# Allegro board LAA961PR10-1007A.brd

Outline 305.8 x 141.25 mm; copper layers: TOP, GND1, IN1, GND2, IN2, IN3, VCC, IN4, GND3, BOTTOM. Coordinates in mm from the lower left corner of the outline.

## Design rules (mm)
net group 18: nets PECI_EC PECI_EC_R
net group DDI1_LANE_P0_C: nets DDI1_LANE_N0_C DDI1_LANE_P0_C
net group DDI1_LANE_P1_C: nets DDI1_LANE_N1_C DDI1_LANE_P1_C
net group DDI1_LANE_P2_C: nets DDI1_LANE_N2_C DDI1_LANE_P2_C
net group DDI1_LANE_P3_C: nets DDI1_LANE_N3_C DDI1_LANE_P3_C
net group DIFFPAIR28: nets SATA_PRX_DKTX_N0_C SATA_PRX_DKTX_P0_C
net group DIFFPAIR29: nets SATA_PTX_DKRX_N0_C SATA_PTX_DKRX_P0_C
net group DOCK_DCIN_IS: nets DOCK_DCIN_IS+ DOCK_DCIN_IS-
net group DP2: nets TMDS_CON_CLK TMDS_CON_CLK#
net group DP4: nets PS8338_AUX PS8338_AUX#
net group DPC_DOCK_LANE_1: nets DPC_DOCK_LANE_N1 DPC_DOCK_LANE_P1
net group DPC_DOCK_LANE_2: nets DPC_DOCK_LANE_N2 DPC_DOCK_LANE_P2
net group DPC_DOCK_LANE_3: nets DPC_DOCK_LANE_N3 DPC_DOCK_LANE_P3
net group GPU_SMBCLK: nets GPU_SMBCLK GPU_SMBDAT
net group HDMI_LANE_0: nets HDMI_LANE_N0 HDMI_LANE_P0
net group HDMI_LANE_1: nets HDMI_LANE_N1 HDMI_LANE_P1
net group HDMI_LANE_2: nets HDMI_LANE_N2 HDMI_LANE_P2
net group HDMI_LANE_3: nets HDMI_LANE_N3 HDMI_LANE_P3
net group I2C1_S_VMM: nets I2C1_SCL_VMM I2C1_SDA_VMM
net group LAN_TX0L: nets LAN_TX0+L LAN_TX0-L
net group LAN_TX1L: nets LAN_TX1+L LAN_TX1-L
net group LAN_TX2L: nets LAN_TX2+L LAN_TX2-L
net group LAN_TX3L: nets LAN_TX3+L LAN_TX3-L
net group MDP_CA_DET: nets MDP_CA_DET MDP_CA_DET#
net group MINI_DP: nets SW_MDP_AUX#_C SW_MDP_AUX_C
net group PCIE_PRX_MMITX_1_C: nets PCIE_PRX_MMITX_N1_C PCIE_PRX_MMITX_P1_C
net group PCIE_PTX_MMIRX_1_C: nets PCIE_PTX_MMIRX_N1_C PCIE_PTX_MMIRX_P1_C
net group REM_DIODE1_: nets REM_DIODE1_N REM_DIODE1_P
net group REM_DIODE2_: nets REM_DIODE2_N REM_DIODE2_P
net group REM_DIODE4_: nets REM_DIODE4_N REM_DIODE4_P
net group SATA_PRX_DTX_P1_RP_C: nets SATA_PRX_DTX_N1_RP_C SATA_PRX_DTX_P1_RP_C
net group SATA_PTX_DRX_N1_RP_C: nets SATA_PTX_DRX_N1_RP_C SATA_PTX_DRX_P1_RP_C
net group SENSE: nets VCCSENSE VSSSENSE
net group SML1_SMBCLK: nets SML1_SMBCLK SML1_SMBDATA
net group TMDS_CON_0: nets TMDS_CON_N0 TMDS_CON_P0
net group TMDS_CON_1: nets TMDS_CON_N1 TMDS_CON_P1
net group TMDS_CON_2: nets TMDS_CON_N2 TMDS_CON_P2
net group USB3RN4_D: nets USB3RN4_D- USB3RP4_D+
net group USB3RP1_D+: nets USB3RN1_D- USB3RP1_D+
net group USB3T1_C: nets USB3TN1_C USB3TP1_C
net group USB3TP1_D+: nets USB3TN1_D- USB3TP1_D+
net group USB3TP4_D: nets USB3TN4_D- USB3TP4_D+
net group USBP0_R_D: nets USBP0_R_D+ USBP0_R_D-
net group USBP4_D: nets USBP4_D+ USBP4_D-
net group 12: nets PCH_OPI_COMP PCH_PCIE_RCOMP SATA_COMP UIM_CLK UIM_DATA UIM_RESET
net group 15: nets DDR3_DRAMRST# DDR3_DRAMRST#_CPU H_PROCHOT# H_PROCHOT#_R H_THERMTRIP# H_THERMTRIP#_R H_VCCST_PWRGD_XDP PCH_AZ_CODEC_BITCLK THERMATRIP2# XDP_OBS0_R XDP_OBS1_R XDP_OBS2_R XDP_OBS3_R XDP_OBS4_R XDP_OBS5_R XDP_OBS6_R XDP_OBS7_R
net group 20: nets DDI2_LANE_N0 DDI2_LANE_N1 DDI2_LANE_N2 DDI2_LANE_N3 DDI2_LANE_P0 DDI2_LANE_P1 DDI2_LANE_P2 DDI2_LANE_P3 DDR_A_DQS0 DDR_A_DQS1 DDR_A_DQS2 DDR_A_DQS3 DDR_A_DQS4 DDR_A_DQS5 DDR_A_DQS6 DDR_A_DQS7 DDR_A_DQS#0 DDR_A_DQS#1 DDR_A_DQS#2 DDR_A_DQS#3 DDR_A_DQS#4 DDR_A_DQS#5 DDR_A_DQS#6 DDR_A_DQS#7 DDR_B_DQS0 DDR_B_DQS1 DDR_B_DQS2 DDR_B_DQS3 DDR_B_DQS4 DDR_B_DQS5 DDR_B_DQS6 DDR_B_DQS7 DDR_B_DQS#0 DDR_B_DQS#1 DDR_B_DQS#2 DDR_B_DQS#3 DDR_B_DQS#4 DDR_B_DQS#5 DDR_B_DQS#6 DDR_B_DQS#7 SD_UHS2_D0N SD_UHS2_D0P SD_UHS2_D1N SD_UHS2_D1P
net group CFG: nets CFG0 CFG1 CFG2 CFG3 CFG3_R CFG4 CFG5 CFG6 CFG7 CFG8 CFG9 CFG10 CFG11 CFG12 CFG13 CFG14 CFG15 CFG16 CFG17 CFG18 CFG19 CFG_RCOMP
net group CL_LINK: nets PCH_CL_CLK1 PCH_CL_DATA1 PCH_CL_RST1#
net group CLK: nets CLK_PCI_DOCK CLK_PCI_LPDEBUG CLK_PCI_MEC PCI_CLK_LPC_0 PCI_CLK_LPC_1 SUSCLK
net group CR_LOW: nets DSWODVREN INTRUDER# PCH_DPWROK PCH_INTVRMEN PCH_PCIE_WAKE# PCH_RSMRST#_Q PCH_RTCRST# PM_APWROK SIO_PWRBTN# SIO_RCIN# SRTCRST# SYS_PWROK SYS_RESET#
net group CRT: nets BLUE_DOCK CLK_DDC2_DOCK DAT_DDC2_DOCK GREEN_DOCK HSYNC_DOCK RED_DOCK VSYNC_DOCK
net group DDRA-ADD: nets DDR_A_BS0 DDR_A_BS1 DDR_A_BS2 DDR_A_CAS# DDR_A_MA0 DDR_A_MA1 DDR_A_MA2 DDR_A_MA3 DDR_A_MA4 DDR_A_MA5 DDR_A_MA6 DDR_A_MA7 DDR_A_MA8 DDR_A_MA9 DDR_A_MA10 DDR_A_MA11 DDR_A_MA12 DDR_A_MA13 DDR_A_MA14 DDR_A_MA15 DDR_A_RAS# DDR_A_WE#
net group DDRA-CLK: nets M_CLK_DDR0 M_CLK_DDR1 M_CLK_DDR#0 M_CLK_DDR#1
net group DDRA-CTL: nets DDR_CKE0_DIMMA DDR_CKE1_DIMMA DDR_CS0_DIMMA# DDR_CS1_DIMMA# M_ODT0 M_ODT1
net group DDRB-ADD: nets DDR_B_BS0 DDR_B_BS1 DDR_B_BS2 DDR_B_CAS# DDR_B_MA0 DDR_B_MA1 DDR_B_MA2 DDR_B_MA3 DDR_B_MA4 DDR_B_MA5 DDR_B_MA6 DDR_B_MA7 DDR_B_MA8 DDR_B_MA9 DDR_B_MA10 DDR_B_MA11 DDR_B_MA12 DDR_B_MA13 DDR_B_MA14 DDR_B_MA15 DDR_B_RAS# DDR_B_WE#
net group DDRB-CLK: nets M_CLK_DDR2 M_CLK_DDR3 M_CLK_DDR#2 M_CLK_DDR#3
net group DDRB-CTL: nets DDR_CKE2_DIMMB DDR_CKE3_DIMMB DDR_CS2_DIMMB# DDR_CS3_DIMMB# M_ODT2 M_ODT3
net group DDRD0_9_20: nets DDR_A_D0 DDR_A_D1 DDR_A_D2 DDR_A_D3 DDR_A_D4 DDR_A_D5 DDR_A_D6 DDR_A_D7 DDR_A_D8 DDR_A_D9 DDR_A_D10 DDR_A_D11 DDR_A_D12 DDR_A_D13 DDR_A_D14 DDR_A_D15 DDR_A_D32 DDR_A_D33 DDR_A_D34 DDR_A_D35 DDR_A_D36 DDR_A_D37 DDR_A_D38 DDR_A_D39 DDR_A_D40 DDR_A_D41 DDR_A_D42 DDR_A_D43 DDR_A_D44 DDR_A_D45 DDR_A_D46 DDR_A_D47 DDR_B_D0 DDR_B_D1 DDR_B_D2 DDR_B_D3 DDR_B_D4 DDR_B_D5 DDR_B_D6 DDR_B_D7 DDR_B_D8 DDR_B_D9 DDR_B_D10 DDR_B_D11 DDR_B_D12 DDR_B_D13 DDR_B_D14 DDR_B_D15 DDR_B_D32 DDR_B_D33 DDR_B_D34 DDR_B_D35 DDR_B_D36 DDR_B_D37 DDR_B_D38 DDR_B_D39 DDR_B_D40 DDR_B_D41 DDR_B_D42 DDR_B_D43 DDR_B_D44 DDR_B_D45 DDR_B_D46 DDR_B_D47
net group DDRD1_9_20: nets DDR_A_D16 DDR_A_D17 DDR_A_D18 DDR_A_D19 DDR_A_D20 DDR_A_D21 DDR_A_D22 DDR_A_D23 DDR_A_D24 DDR_A_D25 DDR_A_D26 DDR_A_D27 DDR_A_D28 DDR_A_D29 DDR_A_D30 DDR_A_D31 DDR_A_D48 DDR_A_D49 DDR_A_D50 DDR_A_D51 DDR_A_D52 DDR_A_D53 DDR_A_D54 DDR_A_D55 DDR_A_D56 DDR_A_D57 DDR_A_D58 DDR_A_D59 DDR_A_D60 DDR_A_D61 DDR_A_D62 DDR_A_D63 DDR_B_D16 DDR_B_D17 DDR_B_D18 DDR_B_D19 DDR_B_D20 DDR_B_D21 DDR_B_D22 DDR_B_D23 DDR_B_D24 DDR_B_D25 DDR_B_D26 DDR_B_D27 DDR_B_D28 DDR_B_D29 DDR_B_D30 DDR_B_D31 DDR_B_D48 DDR_B_D49 DDR_B_D50 DDR_B_D51 DDR_B_D52 DDR_B_D53 DDR_B_D54 DDR_B_D55 DDR_B_D56 DDR_B_D57 DDR_B_D58 DDR_B_D59 DDR_B_D60 DDR_B_D61 DDR_B_D62 DDR_B_D63
net group DP: nets CPU_DPB_AUX CPU_DPB_AUX# CPU_DPC_AUX CPU_DPC_AUX# PS8338_N0 PS8338_N0_C PS8338_N1 PS8338_N1_C PS8338_N2 PS8338_N2_C PS8338_N3 PS8338_N3_C PS8338_P0 PS8338_P0_C PS8338_P1 PS8338_P1_C PS8338_P2 PS8338_P2_C PS8338_P3 PS8338_P3_C VMM2320_AUX VMM2320_AUX# VMM2320_AUX#_C VMM2320_AUX_C VMM2320_N0 VMM2320_N0_C VMM2320_N1 VMM2320_N1_C VMM2320_N2 VMM2320_N2_C VMM2320_N3 VMM2320_N3_C VMM2320_P0 VMM2320_P0_C VMM2320_P1 VMM2320_P1_C VMM2320_P2 VMM2320_P2_C VMM2320_P3 VMM2320_P3_C
net group DPB: nets DPB_CA_DET DPB_CA_DET# DPB_DOCK_AUX DPB_DOCK_AUX# DPB_DOCK_LANE_N0 DPB_DOCK_LANE_N1 DPB_DOCK_LANE_N2 DPB_DOCK_LANE_N3 DPB_DOCK_LANE_P0 DPB_DOCK_LANE_P1 DPB_DOCK_LANE_P2 DPB_DOCK_LANE_P3 DPB_LANE_N0 DPB_LANE_N0_C DPB_LANE_N1 DPB_LANE_N1_C DPB_LANE_N2 DPB_LANE_N2_C DPB_LANE_N3 DPB_LANE_N3_C DPB_LANE_P0 DPB_LANE_P0_C DPB_LANE_P1 DPB_LANE_P1_C DPB_LANE_P2 DPB_LANE_P2_C DPB_LANE_P3 DPB_LANE_P3_C SW_DPB_AUX SW_DPB_AUX# SW_DPB_AUX#_C SW_DPB_AUX_C VMM_DPB_CTRLCLK VMM_DPB_CTRLDAT
net group DPC: nets DPC_CA_DET DPC_CA_DET# DPC_DOCK_AUX DPC_DOCK_AUX# DPC_DOCK_LANE_N0 DPC_DOCK_LANE_P0 DPC_LANE_N0 DPC_LANE_N0_C DPC_LANE_N1 DPC_LANE_N1_C DPC_LANE_N2 DPC_LANE_N2_C DPC_LANE_N3 DPC_LANE_N3_C DPC_LANE_P0 DPC_LANE_P0_C DPC_LANE_P1 DPC_LANE_P1_C DPC_LANE_P2 DPC_LANE_P2_C DPC_LANE_P3 DPC_LANE_P3_C SW_DPC_AUX SW_DPC_AUX# SW_DPC_AUX#_C SW_DPC_AUX_C VMM_DPC_CTRLCLK VMM_DPC_CTRLDAT
net group EDP: nets EDP_CPU_AUX EDP_CPU_AUX# EDP_CPU_AUX#_C EDP_CPU_AUX_C EDP_CPU_LANE_N0 EDP_CPU_LANE_N0_C EDP_CPU_LANE_N1 EDP_CPU_LANE_N1_C EDP_CPU_LANE_P0 EDP_CPU_LANE_P0_C EDP_CPU_LANE_P1 EDP_CPU_LANE_P1_C
net group HDA: nets PCH_AZ_BITCLK PCH_AZ_CODEC_RST# PCH_AZ_CODEC_SDIN0 PCH_AZ_CODEC_SDOUT PCH_AZ_CODEC_SYNC PCH_AZ_RST# PCH_AZ_SDIN0_R PCH_AZ_SDOUT PCH_AZ_SYNC
net group HDMI: nets CPU_DPB_CTRLCLK CPU_DPB_CTRLDAT DDI1_LANE_N0 DDI1_LANE_N1 DDI1_LANE_N2 DDI1_LANE_N3 DDI1_LANE_P0 DDI1_LANE_P1 DDI1_LANE_P2 DDI1_LANE_P3
net group HEADPHONE JACK: nets AUD_HP_OUT_L AUD_HP_OUT_R AUD_OUT_L AUD_OUT_R
net group LAN-NO REFER: nets NB_LAN_TX0+ NB_LAN_TX0- NB_LAN_TX1+ NB_LAN_TX1- NB_LAN_TX2+ NB_LAN_TX2- NB_LAN_TX3+ NB_LAN_TX3-
net group LPC: nets LPC_LAD0 LPC_LAD1 LPC_LAD2 LPC_LAD3 LPC_LFRAME#
net group MDI: nets DOCK_LOM_TRD0+ DOCK_LOM_TRD0- DOCK_LOM_TRD1+ DOCK_LOM_TRD1- DOCK_LOM_TRD2+ DOCK_LOM_TRD2- DOCK_LOM_TRD3+ DOCK_LOM_TRD3- LAN_TX0+ LAN_TX0- LAN_TX1+ LAN_TX1- LAN_TX2+ LAN_TX2- LAN_TX3+ LAN_TX3- SW_LAN_TX0+ SW_LAN_TX0- SW_LAN_TX1+ SW_LAN_TX1- SW_LAN_TX2+ SW_LAN_TX2- SW_LAN_TX3+ SW_LAN_TX3-
net group MINI DP: nets CPU_DPC_CTRLCLK CPU_DPC_CTRLDAT MDP_AUX#_C MDP_AUX_C MDP_LANE_N0_C MDP_LANE_N1_C MDP_LANE_N2_C MDP_LANE_N3_C MDP_LANE_P0_C MDP_LANE_P1_C MDP_LANE_P2_C MDP_LANE_P3_C
net group PCIE: nets PCIE_PRX_GLANTX_N3 PCIE_PRX_GLANTX_N3_C PCIE_PRX_GLANTX_P3 PCIE_PRX_GLANTX_P3_C PCIE_PRX_MMITX_N1 PCIE_PRX_MMITX_P1 PCIE_PRX_SATATX_N6_L0 PCIE_PRX_SATATX_N6_L1 PCIE_PRX_SATATX_P6_L0 PCIE_PRX_SATATX_P6_L1 PCIE_PRX_WIGIGTX_N5 PCIE_PRX_WIGIGTX_P5 PCIE_PRX_WLANTX_N4 PCIE_PRX_WLANTX_P4 PCIE_PTX_GLANRX_N3 PCIE_PTX_GLANRX_N3_C PCIE_PTX_GLANRX_P3 PCIE_PTX_GLANRX_P3_C PCIE_PTX_MMIRX_N1 PCIE_PTX_MMIRX_P1 PCIE_PTX_SATARX_N6_L0 PCIE_PTX_SATARX_N6_L0_C PCIE_PTX_SATARX_N6_L1 PCIE_PTX_SATARX_N6_L1_C PCIE_PTX_SATARX_P6_L0 PCIE_PTX_SATARX_P6_L0_C PCIE_PTX_SATARX_P6_L1 PCIE_PTX_SATARX_P6_L1_C PCIE_PTX_WIGIGRX_N5 PCIE_PTX_WIGIGRX_N5_C PCIE_PTX_WIGIGRX_P5 PCIE_PTX_WIGIGRX_P5_C PCIE_PTX_WLANRX_N4 PCIE_PTX_WLANRX_N4_C PCIE_PTX_WLANRX_P4 PCIE_PTX_WLANRX_P4_C
net group POWER: nets +1.35V_MEM
net group RCOMP: nets SM_RCOMP0 SM_RCOMP1 SM_RCOMP2
net group SATA: nets SATA_PRX_DKTX_N0 SATA_PRX_DKTX_P0 SATA_PRX_DTX_N1 SATA_PRX_DTX_P1 SATA_PTX_DKRX_N0 SATA_PTX_DKRX_P0 SATA_PTX_DRX_N1 SATA_PTX_DRX_P1
net group SD_10_15: nets SD/MMCCD# SD/MMCCLK SD/MMCCLK_R SD/MMCCMD SD/MMCDAT0 SD/MMCDAT1 SD/MMCDAT2 SD/MMCDAT2_R SD/MMCDAT3 SD/MMCDAT3_R SDWP
net group SMB_10: nets BC_CLK_ECE1117 BC_CLK_ECE5048 CHARGER_SMBCLK CHARGER_SMBDAT DDR_XDP_WAN_SMBCLK DDR_XDP_WAN_SMBDAT DOCK_SMB_CLK DOCK_SMB_DAT LAN_SMBCLK LAN_SMBDATA MEM_SMBCLK MEM_SMBDATA PBAT_SMBCLK PBAT_SMBDAT USH_SMBCLK USH_SMBDAT
net group SPI: nets PCH_SPI_CLK PCH_SPI_CS0# PCH_SPI_CS1# PCH_SPI_DIN PCH_SPI_DO PCH_SPI_DO2 PCH_SPI_DO3 SPI_CLK64 SPI_DIN32 SPI_DIN64 SPI_DO32 SPI_DO64 SPI_PCH_CS0#_R SPI_PCH_CS1#_R SPI_PCH_DO2_32 SPI_PCH_DO2_64 SPI_PCH_DO3_32 SPI_PCH_DO3_64
net group SPI_CLK: nets SPI_CLK32
net group SPK: nets INT_SPK_L+ INT_SPK_L- INT_SPK_R+ INT_SPK_R- INT_SPKR_L+ INT_SPKR_L- INT_SPKR_R+ INT_SPKR_R-
net group SRC_CLK: nets CLK_PCIE_LAN CLK_PCIE_LAN# CLK_PCIE_MMI CLK_PCIE_MMI# CLK_PCIE_SATA CLK_PCIE_SATA# CLK_PCIE_WIGIG CLK_PCIE_WIGIG# CLK_PCIE_WLAN CLK_PCIE_WLAN#
net group SVID: nets H_CPU_SVIDALRT# VIDALERT_N VIDSCLK VIDSOUT
net group USB20: nets DOCK_USB3RN1 DOCK_USB3RP1 DOCK_USB3TN1 DOCK_USB3TP1 DOCK_USBP0+ DOCK_USBP0- DOCK_USBP3+ DOCK_USBP3- PS_USBP0_D+ PS_USBP0_D- SW_USB3RN1 SW_USB3RP1 SW_USB3TN1 SW_USB3TP1 SW_USBP0+ SW_USBP0- SW_USBP3+ SW_USBP3- USBP0+ USBP0- USBP1+ USBP1- USBP2+ USBP2- USBP3+ USBP3- USBP3_D+ USBP3_D- USBP4+ USBP4- USBP5+ USBP5- USBP5_D+ USBP5_D- USBP6+ USBP6- USBP7+ USBP7-
net group USB30: nets USB3RN1 USB3RN2 USB3RN2_IO USB3RN2_RP USB3RN4 USB3RP1 USB3RP2 USB3RP2_IO USB3RP2_RP USB3RP4 USB3TN1 USB3TN2 USB3TN4 USB3TN4_C USB3TP1 USB3TP2 USB3TP4 USB3TP4_C
net group WIGIG: nets WIGIG_AUX WIGIG_AUX# WIGIG_AUX#_C WIGIG_AUX_C WIGIG_LANE_N0 WIGIG_LANE_N0_C WIGIG_LANE_N1 WIGIG_LANE_N1_C WIGIG_LANE_N2 WIGIG_LANE_N2_C WIGIG_LANE_N3 WIGIG_LANE_N3_C WIGIG_LANE_P0 WIGIG_LANE_P0_C WIGIG_LANE_P1 WIGIG_LANE_P1_C WIGIG_LANE_P2 WIGIG_LANE_P2_C WIGIG_LANE_P3 WIGIG_LANE_P3_C
nets with their own width: min track width 0.102; nets +CAP_LDO
nets with their own width: min track width 0.254; nets +DCPRRTC +PCH_RTC_VCCSUS3_3 +RTC_CELL_VBAT +VR_CAP +VREFOUT AUD_SENSE_B CLK_BIASREF
nets with their own width: min track width 0.381; nets +PCH_ASATA3PLL +PCH_AUSB3PLL +PCH_VCCACLKPLL +PCH_VCCDSW +PCH_VCCDSW_R +RTC_CELL
nets with their own width: min track width 0.508; nets +0.675V_P +1.05V_M +1.05V_MODPHY_PCH +1.05V_MP +1.05V_RUN +1.05V_RUN_VMM +1.05V_VCCST +1.35V_MEN_P +3.3V_ALW +3.3V_ALW2 +3.3V_ALW_UE2 +3.3V_ALWP +3.3V_RTC_LDO +3.3V_RUN +3.3V_RUN_VDDA +3.3V_RUN_VMM +3.3V_SPI +3.3V_WWAN +5V_ALW +5V_ALW2 +5V_ALWP +5V_RUN +AUX_LDO +COINCELL +DC_IN +DC_IN_SS +DCIN +DCIN_JACK +DIMM1_VREF_DQ +DIMM2_VREF_DQ +DOCK_PWR_BAR +LOM_VCT +NBDOCK_DC_IN_SS +PCH_VCC1P05 +PWR_SRC +PWR_SRC_AC +RSVD_VCC3P3_1 +SD_IO_LDO +SDC_IN +SM_VREF_CA +SM_VREF_CA_DIMM +SM_VREF_DQ0 +SM_VREF_DQ1 +V1.05S_APLLOPI +V1.05SP_B+ +V_DDR_REF +VCC_CORE +VCC_PWR_SRC +VCCIO_OUT +VCCIOA_OUT +VCHGR +VLDOIN_1.35V EDP_COMP GND GNDA GNDA_CHG
nets with their own width: min track width 0.762; nets +1.05V_MODPHY +3.3V_RUN_AUDIO +VDDA_AVDD1
nets with their own width: min track width 1.016; nets +0.9V_LAN +1.2V_LDO +1.05V_VMM_VDD +1.8V_RUN_CARD +3.3V_ALW_PCH +3.3V_CAM +3.3V_LAN +3.3V_M +3.3V_RUN_CARD +3.3V_RUN_VDDIO +3.3V_TP +GND_CHASSIS +PCH_VCCDSW3_3 +SIM_PWR +VDDA_PVDD +VDISPLAY_VCC +VHDMI_VCC RING2 SLEEVE
nets with their own width: min track width 2.032; nets +0.675V_DDR_VTT +1.05V_VMM_VDDTX +3.3V_HDD +3.3V_SUS +3.3V_WLAN +5V_HDD +5V_RUN_AUDIO +BL_PWR_SRC +LCDVDD
nets with their own width: min track width 5.588; nets +PBATT PBATT+_C

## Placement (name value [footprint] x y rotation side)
C33  4.7U_0805_25V6-K  [C_0805]  146.19 136.44 90 top
C42  4.7P_0402_50V8C  [C_0402]  160.42 124.29 90 bottom
C43  4.7P_0402_50V8C  [C_0402]  164.23 124.31 90 bottom
C263  1U_0402_6.3V6K  [C_0402]  69.54 18.38 90 top
C294  0.1U_0402_10V7K  [C_0402]  144.27 127.61 90 top
C295  0.1U_0402_10V7K  [C_0402]  144.47 123.45 270 bottom
C296  0.1U_0402_10V7K  [C_0402]  145.16 127.61 90 top
C297  0.1U_0402_10V7K  [C_0402]  145.35 123.45 270 bottom
C298  0.1U_0402_10V7K  [C_0402]  146.05 127.61 90 top
C299  0.1U_0402_10V7K  [C_0402]  146.24 123.45 270 bottom
C300  0.1U_0402_10V7K  [C_0402]  148.91 123.45 270 bottom
C301  0.1U_0402_10V7K  [C_0402]  149.8 123.45 270 bottom
C302  0.1U_0402_10V7K  [C_0402]  143.58 123.45 270 bottom
C303  0.1U_0402_10V7K  [C_0402]  146.94 127.61 90 top
C304  0.1U_0402_10V7K  [C_0402]  147.13 123.45 270 bottom
C305  0.1U_0402_10V7K  [C_0402]  147.83 127.61 90 top
C306  0.1U_0402_10V7K  [C_0402]  148.02 123.45 270 bottom
C307  0.1U_0402_10V7K  [C_0402]  148.72 127.61 90 top
C308  0.1U_0402_10V7K  [C_0402]  149.61 127.61 90 top
C309  0.1U_0402_10V7K  [C_0402]  150.5 127.61 90 top
C310  0.033U_0402_16V7K  [C_0402]  151.2 125.23 270 bottom
C311  0.033U_0402_16V7K  [C_0402]  150.51 136.26 180 top
C312  0.01U_0402_16V7K  [C_0402]  150.87 133.72 0 top
C313  0.01U_0402_16V7K  [C_0402]  150.87 134.61 0 top
C314  0.01U_0402_16V7K  [C_0402]  150 133.28 180 top
C315  0.01U_0402_16V7K  [C_0402]  150 132.39 180 top
C316  1U_0402_6.3V6K  [C_0402]  172.71 125.28 0 bottom
C317  0.1U_0603_50V7K  [C_0603]  142.5 134.55 0 top
C318  0.1U_0603_50V7K  [C_0603]  144.72 136.58 90 top
C319  4.7P_0402_50V8C  [C_0402]  174.54 124.46 90 bottom
CA5  100P_0402_50V8J  [C_0402]  107.7 126.55 0 bottom
CA6  100P_0402_50V8J  [C_0402]  107.7 125.34 0 bottom
CA7  0.1U_0402_25V6  [C_0402]  102.12 116.59 270 top
CA8  0.1U_0402_25V6  [C_0402]  211.69 68.02 270 top
CA9  10U_0603_6.3V6M  [C_0603]  212.74 67.94 270 top
CA10  4.7U_0603_6.3V6K  [C_0603]  201.7 73.5 180 top
CA11  0.1U_0402_25V6  [C_0402]  202 69.12 180 top
CA16  4.7U_0603_6.3V6K  [C_0603]  210.14 77.11 0 top
CA17  0.1U_0402_25V6  [C_0402]  212.45 75.71 90 top
CA18  4.7U_0603_6.3V6K  [C_0603]  213.5 75.76 90 top
CA19  1000P_0402_50V7K  [C_0402]  203.99 76.58 90 top
CA22  1000P_0402_50V7K  [C_0402]  206.66 76.6 90 top
CA23  1000P_0402_50V7K  [C_0402]  205.77 76.58 90 top
CA24  1000P_0402_50V7K  [C_0402]  204.89 76.59 90 top
CA25  10U_0603_6.3V6M  [C_0603]  215.23 69.88 0 top
CA26  1U_0603_10V4Z  [C_0603]  210.11 66.27 270 top
CA27  0.1U_0402_25V6  [C_0402]  200.63 67.34 0 top
CA28  0.1U_0402_25V6  [C_0402]  200.63 66.47 0 top
CA29  1U_0603_10V6K  [C_0603]  211.66 74.25 0 top
CA30  22P_0402_50V8J  [C_0402]  199.91 74.54 180 top
CA31  1U_0603_10V6K  [C_0603]  200.8 76.24 180 top
CA33  15P_0402_50V8J  [C_0402]  199.95 71.33 180 top
CA35  2.2U_0402_6.3V6M  [C_0402]  211.7 65.33 90 top
CA41  0.1U_0402_25V6  [C_0402]  199.35 63.74 90 top
CA43  4.7U_0603_6.3V6K  [C_0603]  206.34 66.08 270 top
CA44  4.7U_0603_6.3V6K  [C_0603]  207.56 66.02 270 top
CA45  0.1U_0402_25V6  [C_0402]  207.55 76.29 90 top
CA46  10U_0603_6.3V6M  [C_0603]  197.49 79.49 90 top
CA47  0.1U_0402_25V6  [C_0402]  203.1 76.57 90 top
CA48  10U_0603_6.3V6M  [C_0603]  199.19 79.53 90 top
CA49  1U_0603_10V6K  [C_0603]  213.08 73.05 180 top
CA50  0.1U_0402_25V6  [C_0402]  201.77 72.46 180 top
CA51  4.7U_0603_6.3V6K  [C_0603]  208.87 66.18 270 top
CA52  4.7U_0603_6.3V6K  [C_0603]  210.14 75.9 0 top
CA53  4.7U_0603_6.3V6K  [C_0603]  200.08 70.2 270 top
CC1  15P_0402_50V8J  [C_0402]  144.73 63.68 180 bottom
CC2  15P_0402_50V8J  [C_0402]  146.32 60.44 180 bottom
CC3  1U_0402_6.3V6K  [C_0402]  164.07 63.6 180 top
CC4  1U_0402_6.3V6K  [C_0402]  164.07 64.51 180 top
CC5  27P_0402_50V8J  [C_0402]  135.86 60.82 0 bottom
CC6  0.1U_0402_25V6  [C_0402]  175.53 77.08 180 top
CC7  0.1U_0402_25V6  [C_0402]  183.52 78.34 90 bottom
CC8  15P_0402_50V8J  [C_0402]  124.25 100.43 90 top
CC9  33P_0402_50V8J  [C_0402]  193.83 74.68 180 top
CC10  33P_0402_50V8J  [C_0402]  172.76 74.67 180 top
CC11  15P_0402_50V8J  [C_0402]  124.25 99.13 270 top
CC12  12P_0402_50V8J  [C_0402]  163.17 57.98 90 top
CC13  12P_0402_50V8J  [C_0402]  167.58 59.66 180 top
CC14  12P_0402_50V8J  [C_0402]  161.67 55.86 90 top
CC15  12P_0402_50V8J  [C_0402]  165.06 55.77 90 top
CC17  0.1U_0402_25V6  [C_0402]  62.28 65.64 270 top
CC18  0.1U_0402_25V6  [C_0402]  64.56 42.28 180 top
CC19  0.1U_0402_25V6  [C_0402]  65.85 55.98 90 top
CC20  22P_0402_50V8J  [C_0402]  83.76 101.7 0 top
CC21  0.1U_0402_25V6  [C_0402]  67.69 55.98 90 top
CC22  0.1U_0402_25V6  [C_0402]  69.04 38.51 270 top
CC23  22U_0603_6.3V6M  [C_0603]  107.48 76.85 270 top
CC24  100P_0402_50V8J  [C_0402]  95.67 94.67 180 bottom
CC25  2.2U_0402_6.3V6M  [C_0402]  110.47 60.62 90 bottom
CC26  2.2U_0402_6.3V6M  [C_0402]  109.07 60.62 90 bottom
CC27  2.2U_0402_6.3V6M  [C_0402]  117.7 63.05 0 bottom
CC28  2.2U_0402_6.3V6M  [C_0402]  109.4 63.05 180 bottom
CC29  10U_0603_6.3V6M  [C_0603]  111.55 60.57 90 bottom
CC30  10U_0603_6.3V6M  [C_0603]  115.74 60.57 90 bottom
CC31  10U_0603_6.3V6M  [C_0603]  107.99 60.57 90 bottom
CC32  10U_0603_6.3V6M  [C_0603]  114.34 60.57 90 bottom
CC33  10U_0603_6.3V6M  [C_0603]  112.95 60.57 90 bottom
CC34  10U_0603_6.3V6M  [C_0603]  117.52 60.57 90 bottom
CC35  0.1U_0402_25V6  [C_0402]  76.14 82.02 90 top
CC36  22U_0603_6.3V6M  [C_0603]  123.68 58.98 180 top
CC37  1U_0402_6.3V6K  [C_0402]  122.24 76.97 270 top
CC39  330U_D3_2.5VY_R6M  [C_D2]  167.29 62.28 180 bottom
CC40  1U_0402_6.3V6K  [C_0402]  133.09 84.38 180 top
CC41  330U_D3_2.5VY_R6M  [C_D3]  128.24 114.29 0 bottom
CC42  330U_D3_2.5VY_R6M  [C_D3]  138.61 109.72 90 bottom
CC43  1U_0402_6.3V6K  [C_0402]  127.78 97.37 180 top
CC44  1U_0402_6.3V6K  [C_0402]  131.68 83.06 270 top
CC47  22U_0603_6.3V6M  [C_0603]  130.62 96.69 0 bottom
CC48  0.1U_0402_10V7K  [C_0402]  164.96 53.95 90 top
CC49  0.1U_0402_10V7K  [C_0402]  133.16 75.73 180 top
CC50  1U_0402_6.3V6K  [C_0402]  164.04 53.95 90 top
CC51  22U_0603_6.3V6M  [C_0603]  130.62 97.91 0 bottom
CC52  0.1U_0402_10V7K  [C_0402]  159.68 79.21 180 bottom
CC53  1U_0402_6.3V6K  [C_0402]  133.2 82.62 270 top
CC54  0.1U_0402_10V7K  [C_0402]  133.27 79.3 180 top
CC55  22U_0603_6.3V6M  [C_0603]  134.8 97.79 90 bottom
CC56  22U_0603_6.3V6M  [C_0603]  133.53 97.79 90 bottom
CC57  0.1U_0402_10V7K  [C_0402]  130.14 75.03 90 top
CC58  1U_0402_6.3V6K  [C_0402]  133.26 77.14 90 top
CC59  1U_0402_6.3V6K  [C_0402]  131.31 84.38 180 top
CC60  10U_0603_6.3V6M  [C_0603]  125.75 95.72 270 top
CC61  1U_0402_6.3V6K  [C_0402]  131.32 76.43 90 top
CC62  22U_0603_6.3V6M  [C_0603]  158.09 75.66 270 bottom
CC63  22U_0603_6.3V6M  [C_0603]  131.43 78.41 180 top
CC64  22U_0603_6.3V6M  [C_0603]  131.43 79.62 180 top
CC65  1U_0402_6.3V6K  [C_0402]  126.16 58.23 270 top
CC66  0.1U_0402_10V7K  [C_0402]  130.22 83.06 270 top
CC67  100U_1206_6.3V6M  [C_1206]  123.89 98.42 180 bottom
CC68  1U_0402_6.3V6K  [C_0402]  127.39 79.31 270 top
CC69  1U_0402_6.3V6K  [C_0402]  131.25 80.7 180 top
CC70  1U_0402_6.3V6K  [C_0402]  128.44 84.52 270 top
CC71  1U_0402_6.3V6K  [C_0402]  126.03 82.05 270 top
CC72  1U_0402_6.3V6K  [C_0402]  128.8 77.38 0 top
CC73  1U_0402_6.3V6K  [C_0402]  131.5 57.72 270 top
CC77  100U_1206_6.3V6M  [C_1206]  129.16 98.33 90 bottom
CC78  1U_0402_6.3V6K  [C_0402]  128.98 95.95 0 top
CC79  22U_0603_6.3V6M  [C_0603]  124.34 102.48 180 top
CC80  1U_0402_6.3V6K  [C_0402]  142.71 75.26 0 top
CC81  100U_1206_6.3V6M  [C_1206]  119.89 97.08 180 bottom
CC82  1U_0402_6.3V6K  [C_0402]  126 95.56 180 bottom
CC83  100P_0402_50V8J  [C_0402]  93.8 93.62 90 top
CC84  22U_0603_6.3V6M  [C_0603]  126.88 111.18 180 bottom
CC85  22U_0603_6.3V6M  [C_0603]  127.04 94.89 0 top
CC97  0.47U_0402_10V6K  [C_0402]  132.93 74.41 270 top
CC100  1U_0402_6.3V6K  [C_0402]  145.94 76.09 180 top
CC101  0.1U_0402_25V6  [C_0402]  131.09 60.53 0 bottom
CD1  0.1U_0402_25V6  [C_0402]  56.53 33.07 180 top
CD2  1U_0402_6.3V6K  [C_0402]  95.95 32.64 270 top
CD3  1U_0402_6.3V6K  [C_0402]  95.7 23.22 90 top
CD4  1U_0402_6.3V6K  [C_0402]  84.14 23.54 90 top
CD5  2.2U_0402_6.3V6M  [C_0402]  56.53 32.19 180 top
CD6  0.1U_0402_25V6  [C_0402]  65.6 23.47 90 top
CD7  1U_0402_6.3V6K  [C_0402]  81.73 32.64 270 top
CD8  1U_0402_6.3V6K  [C_0402]  92.52 32.64 270 top
CD9  1U_0402_6.3V6K  [C_0402]  81.03 23.47 90 top
CD10  1U_0402_6.3V6K  [C_0402]  85.41 32.64 270 top
CD11  1U_0402_6.3V6K  [C_0402]  90.15 23.56 90 top
CD12  10U_0603_6.3V6M  [C_0603]  82.43 23.23 90 top
CD13  10U_0603_6.3V6M  [C_0603]  85.92 23.23 90 top
CD14  10U_0603_6.3V6M  [C_0603]  83.51 32.88 270 top
CD15  10U_0603_6.3V6M  [C_0603]  87.06 32.88 270 top
CD16  10U_0603_6.3V6M  [C_0603]  90.62 32.88 270 top
CD17  10U_0603_6.3V6M  [C_0603]  89.03 23.23 90 top
CD18  10U_0603_6.3V6M  [C_0603]  87.76 23.23 90 top
CD19  10U_0603_6.3V6M  [C_0603]  94.3 32.88 270 top
CD20  330U_D3_2.5VY_R6M  [C_D3]  104.98 36.57 180 top
CD21  0.022U_0402_16V7K  [C_0402]  56.58 36.3 90 top
CD22  0.1U_0402_25V6  [C_0402]  97.48 23.47 90 top
CD23  2.2U_0402_6.3V6M  [C_0402]  96.59 23.47 90 top
CD24  0.1U_0402_25V6  [C_0402]  121.4 30.53 0 top
CD25  0.1U_0402_25V6  [C_0402]  121.4 31.42 0 top
CD26  0.1U_0402_25V6  [C_0402]  120.54 25.39 180 top
CD27  0.1U_0402_25V6  [C_0402]  120.54 24.44 180 top
CD28  10U_0603_6.3V6M  [C_0603]  121.41 29.45 0 top
CD29  10U_0603_6.3V6M  [C_0603]  120.78 23.3 180 top
CD30  0.1U_0402_25V6  [C_0402]  97.86 11.34 90 top
CD31  2.2U_0402_6.3V6M  [C_0402]  119.19 32.43 90 top
CD32  0.1U_0402_25V6  [C_0402]  120.08 32.43 90 top
CD33  2.2U_0402_6.3V6M  [C_0402]  131.47 31.77 180 top
CD34  0.1U_0402_25V6  [C_0402]  131.47 32.66 180 top
CD35  0.1U_0402_25V6  [C_0402]  137.29 19.89 180 bottom
CD36  0.022U_0402_16V7K  [C_0402]  72.08 24.43 90 top
CD37  1U_0402_6.3V6K  [C_0402]  168.7 23.47 90 top
CD38  1U_0402_6.3V6K  [C_0402]  172.38 23.47 90 top
CD39  1U_0402_6.3V6K  [C_0402]  168.44 32.64 270 top
CD40  1U_0402_6.3V6K  [C_0402]  171.87 32.64 270 top
CD41  1U_0402_6.3V6K  [C_0402]  161.59 23.47 90 top
CD42  1U_0402_6.3V6K  [C_0402]  161.33 32.64 270 top
CD43  1U_0402_6.3V6K  [C_0402]  157.6 32.9 0 top
CD44  1U_0402_6.3V6K  [C_0402]  157.22 21.44 180 bottom
CD45  10U_0603_6.3V6M  [C_0603]  165.27 23.23 90 top
CD46  10U_0603_6.3V6M  [C_0603]  163.11 23.23 90 top
CD47  10U_0603_6.3V6M  [C_0603]  159.68 23.23 90 top
CD48  10U_0603_6.3V6M  [C_0603]  166.54 32.88 270 top
CD49  10U_0603_6.3V6M  [C_0603]  170.22 32.88 270 top
CD50  10U_0603_6.3V6M  [C_0603]  170.48 23.23 90 top
CD51  10U_0603_6.3V6M  [C_0603]  159.55 32.82 270 top
CD52  10U_0603_6.3V6M  [C_0603]  162.98 32.88 270 top
CD53  330U_D3_2.5VY_R6M  [C_D3]  126.27 36.63 180 top
CD54  0.022U_0402_16V7K  [C_0402]  127.82 32.71 270 top
CD55  0.1U_0402_25V6  [C_0402]  173.78 23.47 90 top
CD56  2.2U_0402_6.3V6M  [C_0402]  174.67 23.47 90 top
CD57  0.1U_0402_25V6  [C_0402]  196.4 30.92 0 top
CD58  0.1U_0402_25V6  [C_0402]  196.4 30.03 0 top
CD59  0.1U_0402_25V6  [C_0402]  196.46 25.84 0 top
CD60  0.1U_0402_25V6  [C_0402]  196.46 26.72 0 top
CD61  10U_0603_6.3V6M  [C_0603]  196.66 27.68 90 top
CD62  10U_0603_6.3V6M  [C_0603]  196.47 31.99 0 top
CD63  2.2U_0402_6.3V6M  [C_0402]  191.39 34.39 90 top
CD64  0.1U_0402_25V6  [C_0402]  192.34 34.39 90 top
CE1  10U_0603_6.3V6M  [C_0603]  187.26 93.4 180 top
CE2  0.1U_0402_25V6  [C_0402]  177.02 93.93 270 top
CE3  0.1U_0402_25V6  [C_0402]  189.98 104.07 0 top
CE4  0.1U_0402_10V7K  [C_0402]  172.28 103.86 90 top
CE5  0.1U_0402_25V6  [C_0402]  183.84 108.75 90 top
CE6  0.1U_0402_25V6  [C_0402]  176.13 93.93 270 top
CE7  4.7U_0603_6.3V6K  [C_0603]  190.06 102.86 0 top
CE8  0.047U_0402_16V4Z  [C_0402]  183.45 112 270 top
CE9  33P_0402_50V8J  [C_0402]  182.12 92.56 90 top
CE10  1U_0402_6.3V6K  [C_0402]  217.3 80.7 90 top
CE11  0.1U_0402_25V6  [C_0402]  210.15 83.86 270 top
CE12  1U_0402_6.3V6K  [C_0402]  216.41 80.7 90 top
CE13  0.1U_0402_25V6  [C_0402]  207.86 100.31 0 top
CE14  1U_0402_6.3V6K  [C_0402]  208.63 101.65 90 top
CE15  1U_0402_6.3V6K  [C_0402]  205.12 84.46 270 top
CE16  0.1U_0402_25V6  [C_0402]  216.21 84.13 0 top
CE17  0.1U_0402_25V6  [C_0402]  198.26 90.41 180 top
CE18  0.1U_0402_25V6  [C_0402]  203.01 84.47 270 top
CE19  0.1U_0402_25V6  [C_0402]  198.14 97.78 180 top
CE20  0.1U_0402_25V6  [C_0402]  206 84.46 270 top
CE21  10U_0603_6.3V6M  [C_0603]  216.25 83.06 0 top
CE22  0.1U_0402_25V6  [C_0402]  204.35 99.42 90 top
CE23  0.1U_0402_25V6  [C_0402]  213.03 93.46 0 top
CE24  2200P_0402_50V7K  [C_0402]  212.91 95.32 270 top
CE25  0.1U_0402_25V6  [C_0402]  198.3 86.3 180 top
CE26  2200P_0402_50V7K  [C_0402]  214.32 96.21 270 top
CE27  2200P_0402_50V7K  [C_0402]  213.05 96.43 90 top
CE28  22P_0402_50V8J  [C_0402]  208.36 84.38 180 top
CE29  22P_0402_50V8J  [C_0402]  209.24 82.62 270 top
CE30  1U_0402_6.3V6K  [C_0402]  204.22 80.01 270 top
CE31  4.7U_0603_6.3V6K  [C_0603]  213.17 98.42 0 top
CE32  10U_0603_6.3V6M  [C_0603]  75.31 86.86 180 top
CE34  4.7P_0402_50V8C  [C_0402]  203.14 101.16 90 top
CE35  100P_0402_50V8J  [C_0402]  117.01 81.16 270 top
CE36  0.1U_0402_25V6  [C_0402]  201.17 99.42 90 top
CE37  100P_0402_50V8J  [C_0402]  203.65 38.71 0 bottom
CE38  0.1U_0402_25V6  [C_0402]  210.63 99.18 90 top
CE39  100P_0402_50V8J  [C_0402]  85.64 94.91 90 top
CE40  4700P_0402_25V7K  [C_0402]  215.71 96.21 270 top
CE44  1U_0402_6.3V6K  [C_0402]  212.04 78.17 0 top
CE45  1U_0402_6.3V6K  [C_0402]  209.69 79.04 270 top
CE46  100P_0402_50V8J  [C_0402]  195.34 101.12 0 bottom
CI1  100U_1206_6.3V6M  [C_1206]  70.42 122.8 0 bottom
CI3  0.1U_0402_25V6  [C_0402]  70.98 124.32 0 bottom
CI4  0.1U_0402_10V7K  [C_0402]  66.21 116.61 270 top
CI5  0.1U_0402_10V7K  [C_0402]  67.16 116.61 270 top
CI8  100U_1206_6.3V6M  [C_1206]  246.34 122.01 0 bottom
CI10  0.1U_0402_25V6  [C_0402]  241.89 125.02 90 bottom
CI11  10U_0603_6.3V6M  [C_0603]  241.37 120.23 180 bottom
CI12  0.1U_0402_25V6  [C_0402]  241.06 119.19 180 bottom
CI13  10U_0603_6.3V6M  [C_0603]  60.98 117.02 270 top
CI19  0.1U_0402_25V6  [C_0402]  58.85 119.61 90 bottom
CI27  0.1U_0402_10V7K  [C_0402]  227.59 118.16 270 bottom
CI28  0.1U_0402_10V7K  [C_0402]  226.63 118.16 270 bottom
CI29  0.01U_0402_16V7K  [C_0402]  221.95 85.51 90 top
CI30  0.1U_0402_10V7K  [C_0402]  228.41 81.02 0 top
CI31  0.1U_0402_10V7K  [C_0402]  223.73 86.44 270 top
CI32  0.1U_0402_10V7K  [C_0402]  224.64 86.44 270 top
CI33  0.1U_0402_16V4Z  [C_0402]  219.05 60.58 270 top
CI34  0.1U_0402_16V4Z  [C_0402]  219.28 68.06 180 top
CI35  0.1U_0402_16V4Z  [C_0402]  219.28 68.95 180 top
CI38  0.1U_0402_25V6  [C_0402]  126.37 126.43 270 bottom
CI414  0.1U_0402_25V6  [C_0402]  127.18 131.26 0 bottom
CI415  0.1U_0402_25V6  [C_0402]  130.71 132.43 270 bottom
CI416  0.1U_0402_25V6  [C_0402]  133.37 127.46 180 top
CI417  0.1U_0402_25V6  [C_0402]  133.1 134.14 90 top
CI418  0.1U_0402_25V6  [C_0402]  130.6 134.15 90 top
CI419  0.1U_0402_25V6  [C_0402]  130.24 128.48 90 bottom
CI420  4.7U_0603_6.3V6K  [C_0603]  127.54 128.4 90 bottom
CL1  0.1U_0402_10V7K  [C_0402]  200.63 116.42 180 top
CL2  0.1U_0402_10V7K  [C_0402]  200.63 115.53 180 top
CL3  0.1U_0402_10V7K  [C_0402]  208.68 109.25 270 bottom
CL4  10U_0603_6.3V6M  [C_0603]  208.92 110.39 180 bottom
CL5  0.1U_0402_10V7K  [C_0402]  200.46 111.62 90 top
CL6  0.1U_0402_10V7K  [C_0402]  201.37 111.62 90 top
CL7  1U_0603_10V6K  [C_0603]  215.14 119.6 90 bottom
CL8  0.1U_0402_10V7K  [C_0402]  211.65 110.11 270 top
CL9  0.1U_0402_10V7K  [C_0402]  204.87 120.39 180 top
CL10  0.1U_0402_10V7K  [C_0402]  211.11 114.49 90 bottom
CL11  0.1U_0402_10V7K  [C_0402]  203.34 112.64 180 top
CL12  22U_0603_6.3V6M  [C_0603]  204.76 121.55 180 top
CL13  27P_0402_50V8J  [C_0402]  209.1 108.32 0 top
CL14  27P_0402_50V8J  [C_0402]  211.79 108.32 180 top
CL15  0.1U_0402_10V7K  [C_0402]  211.64 124.01 0 top
CL16  0.47U_0603_10V7K  [C_0603]  269.56 133.9 90 bottom
CL17  0.47U_0603_10V7K  [C_0603]  270.76 133.9 90 bottom
CL18  470P_0402_50V7K  [C_0402]  257.94 125.72 0 bottom
CL19  0.1U_0402_10V7K  [C_0402]  257.94 124.77 0 bottom
CL20  0.47U_0603_10V7K  [C_0603]  275.53 126.86 180 top
CL21  0.47U_0603_10V7K  [C_0603]  276.48 126.86 0 top
CL22  150P_1808_2.5KV8J  [C_1808]  260.53 122.61 0 bottom
CL23  0.1U_0402_10V7K  [C_0402]  197.14 105.59 270 top
CL24  470P_0402_50V7K  [C_0402]  198.74 107.39 0 top
CL25  0.1U_0402_25V6  [C_0402]  209.22 120.34 90 top
CL26  0.1U_0402_25V6  [C_0402]  216.22 127.61 90 bottom
CL27  0.1U_0402_25V6  [C_0402]  222.18 125.02 0 bottom
CMOS1  SHORT PADS~D  [SHORTPADS]  84.17 53.65 270 bottom
CN1  10U_0603_6.3V6M  [C_0603]  221.3 113.34 270 top
CN2  0.1U_0402_25V6  [C_0402]  217.6 110.68 270 top
CN13  1000P_0402_50V7K  [C_0402]  215.84 109.2 180 bottom
CN14  0.1U_0402_25V6  [C_0402]  215.84 108.31 180 bottom
CN15  0.1U_0402_25V6  [C_0402]  216.43 108.74 270 top
CN16  0.1U_0402_25V6  [C_0402]  217.42 108.71 270 top
CN35  0.01U_0402_16V7K  [C_0402]  220.82 109.03 90 bottom
CN36  0.01U_0402_16V7K  [C_0402]  221.73 109.03 90 bottom
CN37  0.01U_0402_16V7K  [C_0402]  222.65 109.06 90 bottom
CN38  0.01U_0402_16V7K  [C_0402]  223.56 109.06 90 bottom
CR1  4.7U_0603_6.3V6K  [C_0603]  20.36 11.89 180 top
CR2  0.1U_0402_25V6  [C_0402]  20.89 23.85 90 top
CR3  0.1U_0402_25V6  [C_0402]  20.07 12.96 180 top
CR4  0.1U_0402_25V6  [C_0402]  27.56 19.56 270 top
CR6  0.1U_0402_25V6  [C_0402]  17.22 17.07 180 top
CR7  4.7U_0603_6.3V6K  [C_0603]  17.91 26.22 270 top
CR8  0.1U_0402_25V6  [C_0402]  17.2 23.87 0 top
CR9  4.7U_0603_6.3V6K  [C_0603]  19.24 26.15 270 top
CR10  0.1U_0402_25V6  [C_0402]  19.95 23.8 180 top
CR13  0.1U_0402_25V6  [C_0402]  29.47 18.74 270 top
CR14  4.7U_0603_6.3V6K  [C_0603]  16.32 11.61 90 top
CR15  0.1U_0402_25V6  [C_0402]  17.43 12.11 90 top
CR17  1U_0402_6.3V6K  [C_0402]  17.91 21.89 90 top
CR18  4.7U_0603_6.3V6K  [C_0603]  28.51 25.43 180 top
CR19  0.1U_0402_25V6  [C_0402]  25.54 24.64 270 top
CR21  0.1U_0402_25V6  [C_0402]  22.7 12.94 90 top
CR22  0.1U_0402_25V6  [C_0402]  21.19 12.94 90 top
CR23  5P_0402_50V8C  [C_0402]  29.38 20.51 270 top
CR24  0.1U_0402_10V7K  [C_0402]  23.31 26.55 270 top
CR25  0.1U_0402_10V7K  [C_0402]  24.2 26.55 270 top
CR26  0.1U_0402_10V7K  [C_0402]  22.42 26.55 270 top
CR27  0.1U_0402_10V7K  [C_0402]  21.53 26.55 270 top
CR31  1U_0402_6.3V6K  [C_0402]  17.22 17.96 180 top
CR34  4.7U_0603_6.3V6K  [C_0603]  17.91 15.45 180 top
CR35  0.1U_0402_25V6  [C_0402]  31.74 13.82 270 top
CV1  0.1U_0402_10V7K  [C_0402]  92.65 119.13 270 top
CV2  0.1U_0402_10V7K  [C_0402]  93.56 119.13 270 top
CV3  0.1U_0402_10V7K  [C_0402]  91.76 119.13 270 top
CV4  0.1U_0402_10V7K  [C_0402]  90.87 119.13 270 top
CV5  0.1U_0402_10V7K  [C_0402]  89.98 119.13 270 top
CV6  0.1U_0402_10V7K  [C_0402]  89.09 119.13 270 top
CV7  0.1U_0603_50V7K  [C_0603]  98.44 114.23 180 bottom
CV8  0.1U_0402_25V6  [C_0402]  93.03 114.4 270 bottom
CV9  10U_0603_6.3V6M  [C_0603]  76.08 122.99 180 top
CV10  0.01U_0402_16V7K  [C_0402]  81.54 121.1 270 top
CV11  1000P_0402_50V7K  [C_0402]  89.09 113.13 90 top
CV12  0.1U_0603_50V7K  [C_0603]  92.9 116.26 180 top
CV24  0.1U_0402_16V4Z  [C_0402]  99.88 125.34 0 bottom
CV27  10U_0603_6.3V6M  [C_0603]  95.63 127.71 270 bottom
CV30  0.1U_0402_10V7K  [C_0402]  94.3 127.89 270 bottom
CV60  2.2U_0402_6.3V6M  [C_0402]  117.66 122.36 180 top
CV61  0.01U_0402_16V7K  [C_0402]  117.68 112.46 180 top
CV62  0.01U_0402_16V7K  [C_0402]  125.92 111.48 270 top
CV66  0.1U_0402_25V6  [C_0402]  128.6 123.22 270 top
CV69  0.1U_0402_25V6  [C_0402]  118.63 122.3 90 top
CV71  0.1U_0402_25V6  [C_0402]  116.75 119.68 0 top
CV72  0.1U_0402_25V6  [C_0402]  116.75 118.79 0 top
CV73  0.1U_0402_25V6  [C_0402]  116.75 117.91 0 top
CV74  0.1U_0402_25V6  [C_0402]  116.77 116.99 0 top
CV75  0.1U_0402_25V6  [C_0402]  116.76 116.07 0 top
CV76  0.1U_0402_25V6  [C_0402]  116.76 115.18 0 top
CV77  0.1U_0402_25V6  [C_0402]  116.75 114.27 0 top
CV78  0.1U_0402_25V6  [C_0402]  116.77 113.37 0 top
CV79  0.1U_0402_25V6  [C_0402]  122.42 123.24 270 top
CV80  0.1U_0402_25V6  [C_0402]  123.31 123.24 270 top
CV82  10U_0603_6.3V6M  [C_0603]  158.82 116.32 90 top
CV83  0.1U_0402_25V6  [C_0402]  152.15 113.2 90 top
CV84  0.1U_0402_25V6  [C_0402]  152.78 116.25 90 top
CV85  0.01U_0402_16V7K  [C_0402]  153.89 107.61 270 top
CV86  0.01U_0402_16V7K  [C_0402]  152.15 111.95 270 top
CV87  1U_0603_10V6K  [C_0603]  160.04 116.32 90 top
CV88  0.1U_0402_25V6  [C_0402]  154.88 105.46 0 top
CV89  0.01U_0402_16V7K  [C_0402]  154.94 106.35 0 top
CV90  10U_0603_6.3V6M  [C_0603]  148.78 114.67 180 top
CV91  0.1U_0402_25V6  [C_0402]  153 107.61 270 top
CV92  0.01U_0402_16V7K  [C_0402]  155.37 111.37 0 top
CV93  0.01U_0402_16V7K  [C_0402]  153.67 116.25 90 top
CV94  10U_0603_6.3V6M  [C_0603]  150.05 108.19 0 top
CV95  0.1U_0402_25V6  [C_0402]  149.71 116.24 90 top
CV96  0.01U_0402_16V7K  [C_0402]  157.06 109.27 270 top
CV97  0.01U_0402_16V7K  [C_0402]  154.69 116.25 90 top
CV98  0.01U_0402_16V7K  [C_0402]  150.89 116.24 90 top
CV99  0.01U_0402_16V7K  [C_0402]  155.6 114.65 90 top
CV100  0.1U_0402_25V6  [C_0402]  148.8 112.31 90 top
CV101  10U_0603_6.3V6M  [C_0603]  147.77 112.09 90 top
CV102  0.1U_0402_10V7K  [C_0402]  151.07 103.8 90 bottom
CV103  0.1U_0402_10V7K  [C_0402]  150.18 103.8 90 bottom
CV104  0.1U_0402_10V7K  [C_0402]  152.85 103.8 90 bottom
CV105  0.1U_0402_10V7K  [C_0402]  151.96 103.8 90 bottom
CV106  0.1U_0402_10V7K  [C_0402]  153.74 103.8 90 bottom
CV107  0.1U_0402_10V7K  [C_0402]  154.63 103.8 90 bottom
CV108  0.1U_0402_10V7K  [C_0402]  155.51 103.8 90 bottom
CV109  0.1U_0402_10V7K  [C_0402]  156.4 103.8 90 bottom
CV110  0.1U_0402_10V7K  [C_0402]  149.29 103.8 90 bottom
CV111  0.1U_0402_10V7K  [C_0402]  148.4 103.8 90 bottom
CV113  18P_0402_50V8J  [C_0402]  145.48 106.57 180 bottom
CV114  0.1U_0402_25V6  [C_0402]  158.82 97.6 0 bottom
CV115  22P_0402_50V8J  [C_0402]  144.59 104.8 270 bottom
CV116  470P_0402_50V7K  [C_0402]  139.45 104.94 90 bottom
CV117  470P_0402_50V7K  [C_0402]  138.56 104.94 90 bottom
CV118  0.1U_0402_10V7K  [C_0402]  137.61 106.56 270 bottom
CV119  0.1U_0402_10V7K  [C_0402]  132.03 121.59 180 bottom
CV120  0.1U_0402_10V7K  [C_0402]  132.03 123.69 180 bottom
CV121  0.1U_0402_25V6  [C_0402]  159.79 99.51 180 bottom
CV122  0.1U_0402_10V7K  [C_0402]  162.5 109.26 90 bottom
CV123  0.1U_0402_10V7K  [C_0402]  163.39 109.26 90 bottom
CV124  0.1U_0402_25V6  [C_0402]  141.15 121.15 0 bottom
CV145  0.1U_0402_25V6  [C_0402]  174.55 84.1 270 top
CV146  0.1U_0402_25V6  [C_0402]  175.44 84.1 270 top
CV147  0.1U_0402_25V6  [C_0402]  176.34 84.1 270 top
CV148  0.1U_0402_25V6  [C_0402]  177.23 84.1 270 top
CV149  0.1U_0402_25V6  [C_0402]  175.39 89.25 270 top
CV150  0.1U_0402_25V6  [C_0402]  174.45 89.24 270 top
CV152  0.1U_0402_25V6  [C_0402]  176.28 89.27 270 top
CV153  0.1U_0402_25V6  [C_0402]  177.23 89.25 270 top
CV156  0.1U_0402_25V6  [C_0402]  178.2 89.26 270 top
CV157  0.1U_0402_25V6  [C_0402]  179.15 89.25 270 top
CV501  0.1U_0402_10V7K  [C_0402]  250.27 122.55 0 bottom
CV502  0.1U_0402_10V7K  [C_0402]  250.27 123.43 0 bottom
CV503  0.1U_0402_10V7K  [C_0402]  254.14 125.97 270 bottom
CV504  0.1U_0402_10V7K  [C_0402]  253.23 125.97 270 bottom
CV505  0.1U_0402_10V7K  [C_0402]  244.65 125.94 270 bottom
CV506  0.1U_0402_10V7K  [C_0402]  245.55 125.94 270 bottom
CV507  0.1U_0402_10V7K  [C_0402]  243.78 125.97 270 bottom
CV508  0.1U_0402_10V7K  [C_0402]  242.89 125.97 270 bottom
CV509  .01U_0402_16V7K  [C_0402]  251.76 125.97 270 bottom
CV510  0.1U_0402_16V4Z  [C_0402]  254.97 126.75 270 top
CV511  0.1U_0402_25V6  [C_0402]  235.28 126.29 180 top
CV512  0.1U_0402_10V7K  [C_0402]  234.58 118.94 180 top
CV513  0.1U_0402_10V7K  [C_0402]  234.58 118.05 180 top
CV518  0.1U_0402_10V7K  [C_0402]  140.34 104.94 90 bottom
CV600  0.1U_0402_25V6  [C_0402]  136.91 119.12 180 top
CV601  0.1U_0402_25V6  [C_0402]  139.04 110.63 270 top
CV602  0.1U_0402_25V6  [C_0402]  144.35 110.04 180 top
CV603  0.01U_0402_16V7K  [C_0402]  145.28 121.15 0 top
CV604  0.01U_0402_16V7K  [C_0402]  139.85 122.94 90 top
CV605  2.2U_0402_6.3V6M  [C_0402]  131.54 113.47 180 top
CV606  0.1U_0402_25V6  [C_0402]  131.57 118.98 0 top
CV607  0.1U_0402_25V6  [C_0402]  131.57 118.04 0 top
CV608  0.1U_0402_25V6  [C_0402]  129.59 117.76 0 top
CV609  0.1U_0402_25V6  [C_0402]  129.59 116.84 0 top
CV610  0.1U_0402_25V6  [C_0402]  131.66 116.63 0 top
CV611  0.1U_0402_25V6  [C_0402]  131.66 115.69 0 top
CV612  0.1U_0402_25V6  [C_0402]  129.69 115.45 0 top
CV613  0.1U_0402_25V6  [C_0402]  129.67 114.46 0 top
CZ1  0.1U_0402_25V6  [C_0402]  101.23 116.59 270 top
CZ2  0.1U_0402_16V4Z  [C_0402]  106.47 114.39 180 bottom
CZ4  0.1U_0402_25V6  [C_0402]  190.01 54.84 0 top
CZ5  4700P_0402_25V7K  [C_0402]  180.56 55.53 270 top
CZ6  2200P_0402_50V7K  [C_0402]  179.02 57.13 90 top
CZ7  2200P_0402_50V7K  [C_0402]  189.99 59.24 0 top
CZ9  0.1U_0402_25V6  [C_0402]  191.75 55.72 0 top
CZ10  0.1U_0402_25V6  [C_0402]  223.21 47.86 0 top
CZ11  0.1U_0402_25V6  [C_0402]  222.38 47.87 180 top
CZ12  0.1U_0402_25V6  [C_0402]  220.73 48.8 0 top
CZ13  0.1U_0402_10V7K  [C_0402]  178.67 78.31 90 bottom
CZ14  0.1U_0402_10V7K  [C_0402]  179.56 78.31 90 bottom
CZ15  0.1U_0402_25V6  [C_0402]  169.99 90.27 90 top
CZ16  0.047U_0402_16V4Z  [C_0402]  170.89 89.08 180 top
CZ17  0.1U_0402_25V6  [C_0402]  168.98 91.19 270 top
CZ18  0.1U_0402_25V6  [C_0402]  191.14 87.35 90 bottom
CZ19  4.7U_0603_6.3V6K  [C_0603]  189.11 91.18 180 top
CZ20  0.047U_0402_16V4Z  [C_0402]  168.02 90.27 90 top
CZ21  0.1U_0402_10V7K  [C_0402]  184.53 78.34 90 bottom
CZ22  0.1U_0402_10V7K  [C_0402]  185.49 78.34 90 bottom
CZ23  470P_0402_50V7K  [C_0402]  191.44 51.4 90 top
CZ24  0.1U_0402_10V7K  [C_0402]  189.92 46.29 270 top
CZ25  220P_0402_50V7K  [C_0402]  165.69 79.11 0 top
CZ27  0.1U_0402_25V6  [C_0402]  200.62 57.45 0 top
CZ28  0.1U_0402_25V6  [C_0402]  199.39 57.42 90 top
CZ29  0.1U_0402_25V6  [C_0402]  198.49 57.43 90 top
CZ30  10P_0402_50V8J  [C_0402]  203.34 57.43 180 top
CZ31  10P_0402_50V8J  [C_0402]  204.21 57.42 0 top
CZ32  0.1U_0402_10V7K  [C_0402]  215.48 55.11 90 bottom
CZ33  0.1U_0402_10V7K  [C_0402]  216.44 55.11 90 bottom
CZ34  0.1U_0402_25V6  [C_0402]  182.7 88.99 90 top
CZ35  0.01U_0402_16V7K  [C_0402]  190.32 80.83 180 top
CZ36  0.1U_0402_10V7K  [C_0402]  198.21 110.3 90 top
CZ37  470P_0402_50V7K  [C_0402]  198.74 108.88 0 top
CZ38  10U_0603_6.3V6M  [C_0603]  131.85 104.17 0 top
CZ39  0.1U_0402_10V7K  [C_0402]  137.16 99.48 180 top
CZ40  0.1U_0402_10V7K  [C_0402]  200.4 32.25 0 top
CZ41  470P_0402_50V7K  [C_0402]  198.64 34.09 180 top
CZ42  470P_0402_50V7K  [C_0402]  198.64 34.98 180 top
CZ43  0.1U_0402_10V7K  [C_0402]  200.4 36.69 0 top
CZ44  0.1U_0402_10V7K  [C_0402]  54.51 59.46 180 top
CZ45  470P_0402_50V7K  [C_0402]  54.51 60.35 180 top
CZ46  1000P_0402_50V7K  [C_0402]  54.51 61.31 180 top
CZ47  0.1U_0402_10V7K  [C_0402]  54.51 62.26 180 top
CZ48  0.1U_0402_25V6  [C_0402]  186.74 118.93 0 top
CZ49  470P_0402_50V7K  [C_0402]  190.55 51.41 90 top
CZ50  0.1U_0402_10V7K  [C_0402]  194.43 46.29 270 top
CZ51  0.047U_0402_16V4Z  [C_0402]  227.03 63.4 0 bottom
CZ52  0.047U_0402_16V4Z  [C_0402]  227.03 64.28 0 bottom
CZ53  33P_0402_50V8J  [C_0402]  227 65.15 0 bottom
CZ54  22U_0603_6.3V6M  [C_0603]  200.79 63.17 270 bottom
CZ55  33P_0402_50V8J  [C_0402]  201.87 63.12 270 bottom
CZ56  0.1U_0402_10V7K  [C_0402]  136.2 96.13 0 top
CZ57  150U_B2_6.3VM_R35M  [C_B2]  226.71 61.54 90 bottom
CZ58  0.1U_0402_10V7K  [C_0402]  212.47 55.11 90 bottom
CZ59  0.1U_0402_10V7K  [C_0402]  213.43 55.11 90 bottom
CZ60  470P_0402_50V7K  [C_0402]  136.2 97.02 0 top
CZ62  470P_0402_50V7K  [C_0402]  136.13 97.91 0 top
CZ63  33P_0402_50V8J  [C_0402]  65.6 18.46 90 top
CZ64  33P_0402_50V8J  [C_0402]  68.2 14.23 270 bottom
CZ65  33P_0402_50V8J  [C_0402]  66.49 18.46 90 top
CZ66  47P_0402_50V8J  [C_0402]  189.65 51.4 90 top
CZ68  0.047U_0402_16V4Z  [C_0402]  223.59 46.94 0 top
D19  -  [RB751S40T1G_SOD523-2]  179.77 125.15 180 bottom
D20  -  [L30ESD24VC3-2_SOT23-3]  140.53 137.4 270 top
DA4  -  [RB751S40T1G_SOD523-2]  215.35 72.18 0 top
DA5  -  [RB751S40T1G_SOD523-2]  215.35 71.06 0 top
DA6  -  [L03ESDL5V0CC3-2_SOT23-3]  222.67 8.21 270 top
DA7  -  [L03ESDL5V0CC3-2_SOT23-3]  224.72 12.3 90 top
DE1  -  [RB751S40T1G_SOD523-2]  75.32 88.13 180 top
DI1  -  [L05ESDL5V0NA-4_SLP2510P8-10-9]  65.16 122.46 180 top
DI2  -  [AZC199-02SPR7G_SOT23-3]  67.21 123.12 270 bottom
DI3  -  [AZC199-02SPR7G_SOT23-3]  237.02 123.51 0 bottom
DI6  -  [L05ESDL5V0NA-4_SLP2510P8-10-9]  223.98 123.95 180 bottom
DV1  -  [BAT54CW_SOT323-3]  101.02 119.68 180 top
DV2  -  [BAT54CW_SOT323-3]  103.89 113.33 180 top
DV3  -  [BAT54CW_SOT323-3]  75.17 118.55 270 top
DV4  -  [AZC199-02SPR7G_SOT23-3]  107.32 114.01 0 top
DZ1  -  [RB751S40T1G_SOD523-2]  173.87 106.86 180 top
DZ2  -  [RB751S40T1G_SOD523-2]  168.02 89.15 270 top
DZ3  -  [RB751S40T1G_SOD523-2]  192.79 115.81 90 top
DZ4  -  [RB751S40T1G_SOD523-2]  195.33 115.81 90 top
DZ5  -  [RB751S40T1G_SOD523-2]  200.6 57.18 90 bottom
DZ6  -  [RB751S40T1G_SOD523-2]  190.82 97.91 0 top
FD1  FIDUCIAL MARK~D  [FIDUCIAL_C40M80]  55.41 127.36 0 top
FD2  FIDUCIAL MARK~D  [FIDUCIAL_C40M80]  225.05 22.91 0 top
FD3  FIDUCIAL MARK~D  [FIDUCIAL_C40M80]  55.41 127.36 180 bottom
FD4  FIDUCIAL MARK~D  [FIDUCIAL_C40M80]  222.25 14.66 180 bottom
H1  -  [H_2P8]  51.5 133.95 0 top
H2  -  [H_2P8]  103.5 134.45 0 top
H3  -  [H_2P8]  127.9 138.35 0 top
H4  -  [H_2P8]  217.5 133.45 0 top
H5  -  [H_2P8]  9.1 46.15 0 top
H6  -  [H_2P8]  231 113.25 0 top
H7  -  [H_3P8]  151.25 68.79 0 top
H8  -  [H_3P8]  87.75 68.79 0 top
H9  -  [H_3P8]  87.75 89.11 0 top
H10  -  [H_3P8]  151.25 89.11 0 top
H11  -  [H_2P8]  127.9 106.45 0 top
H12  -  [H_2P8]  193.1 138.35 0 top
H13  -  [H_2P8]  9.7 7.95 0 top
H14  -  [H_2P8]  227.5 17.45 0 top
H15  -  [H_2P8]  45.5 34.05 0 top
H16  -  [H_2P8]  101.35 17.95 0 top
H18  -  [H_3P3]  226.12 52.93 0 top
H19  -  [H_3P3]  73.72 70.25 0 top
H20  -  [H_2P1N]  14.2 7.95 0 top
H21  -  [H_3P1]  213.45 103.75 0 top
H22  -  [H_3P1]  179.55 114.75 0 top
H23  -  [H_2P1X2P6]  262.5 138.75 90 top
H27  -  [H_2P8]  176.75 1.65 0 top
JANT1  ACES_50208-00801-003  [ACES_50208-00801-003_8P]  126.42 119.9 180 bottom
JAPS1  ACES_50506-01841-P01  [ACES_50506-01841-P01_18P-NPM]  220.61 98.2 90 top
JDEG1  ACES_50521-01041-P01  [ACES_50521-01041-P01_10P]  183.75 80.43 0 top
JDIMM1  BELLW_80001-1021  [BELLW_80001-1021_204P]  57.15 32.14 180 bottom
JDIMM2  BELLW_80001-1021  [BELLW_80001-1021_204P]  133.15 32.14 180 bottom
JDOCK1  JAE_WD2F144WB7-DT  [JAE_WD2F144WB7-DT_144P-T]  141.75 128.85 0 bottom
JEDP1  ACES_50398-04041-001  [ACES_50398-04041-001_40P]  106.47 116.18 180 bottom
JFAN1  ACES_50271-0040N-001  [ACES_50271-0040N-001_4P]  80.72 91.9 90 bottom
JHDMI1  LCN_AUF05-1922S10-0019  [LCN_AUF05-1922S10-0019_19P-T]  85.96 132.07 0 bottom
JIO1  ACES_50506-03041-P01  [ACES_50506-03041-P01_30P]  220.7 59.2 90 top
JKBTP1  ACES_50506-01641-P01  [ACES_50506-01641-P01_16P]  197.35 55.05 0 top
JLED1  E-T_4260K-Q06N-23L  [E-T_4260K-Q06N-23L_6P]  116.01 118.45 180 bottom
JLOM1  SANTA_130456-511  [SANTA_130456-511_13P-T]  290.83 129.03 0 bottom
JLPDE1  HB_A531015-SCHR21  [HB_A531015-SCHR21_10P]  160.5 77.91 270 bottom
JMDP1  FOX_3V112M1-RA4A2-7H  [FOX_3V112M1-RA4A2-7H_20P]  245.85 131.84 180 bottom
JNGFF1  BELLW_80148-3221  [BELLW_80148-3221_67P-T]  170.3 81.18 0 bottom
JNGFF2  BELLW_80149-3221  [BELLW_80149-3221_67P]  204.2 58.19 0 bottom
JRTC1  TYCO_2-1775293-2~D  [TYCO_2-1775293-2_2P]  220.5 48.45 0 bottom
JSATA1  E-T_0870K-F20C-22L  [E-T_0870K-F20C-22L_20P]  223.65 111.73 180 bottom
JSD1  T-SOL_156-2000302608_NR-S  [T-SOL_156-2000302608_19P_NR-S]  29.52 22.05 90 bottom
JSIM1  T-SOL_159-1000302602  [T-SOL_159-1000302602_10P-T]  70.42 16.48 0 top
JSPI1  E-T_6700K-Y20N-00L  [E-T_6700K-Y20N-00L_20P]  166.38 69.84 180 bottom
JSPK1  E-T_4280K-F04N-05L  [E-T_4280K-F04N-05L_4P]  230.2 9.55 0 top
JTAG1  @SHORT PADS~D  [SHORTPADS]  203.14 79.68 270 top
JUSB1  TAITW_PUBAU4-09FLBS1FF4H0  [TAITW_PUBAU4-09FLBS1FF4H0_9P]  69.65 127.04 0 bottom
JUSB2  TAITW_PUBAU4-09FLBS1FF4H0  [TAITW_PUBAU4-09FLBS1FF4H0_9P]  232.55 127.04 0 bottom
JUSH1  E-T_6705K-Y20N-00L  [E-T_6705K-Y20N-00L_20P]  225.8 45 0 top
JXDP1  SAMTE_BSH-030-01-L-D-A  [SAMTE_BSH-030-01-L-D-A_60P]  56.25 46.85 0 top
LA5  BLM15PX600SN1D_2P  [MURAT_BLM15PX600SN1D_2P]  216.75 63.89 270 top
LA6  BLM15PX330SN1D_2P  [MURAT_BLM15PX330SN1D_2P]  219.77 8.72 0 top
LA7  BLM15PX330SN1D_2P  [MURAT_BLM15PX330SN1D_2P]  219.72 10.25 0 top
LA8  BLM15PX330SN1D_2P  [MURAT_BLM15PX330SN1D_2P]  219.79 13.23 0 top
LA9  BLM15PX330SN1D_2P  [MURAT_BLM15PX330SN1D_2P]  219.74 11.72 0 top
LC1  2.2UH_LQM2MPN2R2NG0L_30%  [MURAT_LQM2MPN2R2NG0L_2P]  133.58 101.21 180 bottom
LC2  2.2UH_LQM2MPN2R2NG0L_30%  [MURAT_LQM2MPN2R2NG0L_2P]  136.59 99.47 270 bottom
LC3  2.2UH_LQM2MPN2R2NG0L_30%  [MURAT_LQM2MPN2R2NG0L_2P]  136.63 101.21 180 bottom
LC4  2.2UH_LQM2MPN2R2NG0L_30%  [MURAT_LQM2MPN2R2NG0L_2P]  133.58 103.43 180 bottom
LC5  2.2UH_LQM2MPN2R2NG0L_30%  [MURAT_LQM2MPN2R2NG0L_2P]  135.83 103.08 90 bottom
LED5  LTW-193ZDS5_WHITE  [LED_LTW-193ZDS5_2P]  274.5 130.7 0 top
LED6  LTW-193ZDS5_WHITE  [LED_LTW-193ZDS5_2P]  255.5 130.7 0 top
LED7  LTW-295DSKS-5A_YEL-WHITE  [LED_LTW-295DSKS-5A_4P]  265.15 130.34 0 top
LI1  DLW21HN900HQ2L_4P  [MURAT_DLW21HN900HQ2L_4P]  65.51 118.08 90 top
LI2  DLW21HN900HQ2L_4P  [MURAT_DLW21HN900HQ2L_4P]  67.29 118.06 90 top
LI3  DLW21HN900HQ2L_4P  [MURAT_DLW21HN900HQ2L_4P]  61.79 124.11 0 top
LI4  DLW21HN900HQ2L_4P  [MURAT_DLW21HN900HQ2L_4P]  235.96 119.28 0 bottom
LI8  DLW21HN900HQ2L_4P  [MURAT_DLW21HN900HQ2L_4P]  225.4 119.71 90 bottom
LI9  DLW21HN900HQ2L_4P  [MURAT_DLW21HN900HQ2L_4P]  223.8 119.71 90 bottom
LL1  4.7UH_BRC2012T4R7MD_20%  [TAIYO_BRC2012T4R7MD_2P]  209.87 111.65 90 bottom
LV1  BLM15BB221SN1D_2P~D  [MURAT_BLM15BB221SN1D_2P]  99.46 116.34 0 top
LV3  DLW21HN900HQ2L_4P  [MURAT_DLW21HN900HQ2L_4P]  92.05 125.7 90 top
LV6  DLW21HN900HQ2L_4P  [MURAT_DLW21HN900HQ2L_4P]  84.95 125.7 90 top
LV10  DLW21HN900HQ2L_4P  [MURAT_DLW21HN900HQ2L_4P]  88.57 125.7 90 top
LV12  DLW21HN900HQ2L_4P  [MURAT_DLW21HN900HQ2L_4P]  95.8 125.7 90 top
LV22  BLM15PX181SN1D_2P  [MURAT_BLM15PX181SN1D_2P]  159.8 115.04 180 top
LV23  BLM15PX181SN1D_2P  [MURAT_BLM15PX181SN1D_2P]  147.48 116.07 0 top
LV24  BLM15PX181SN1D_2P  [MURAT_BLM15PX181SN1D_2P]  147.74 108.19 0 top
LV25  BLM15PX181SN1D_2P  [MURAT_BLM15PX181SN1D_2P]  147.83 110.95 270 top
LV27  DLW21HN900HQ2L_4P  [MURAT_DLW21HN900HQ2L_4P]  110.21 114.75 0 top
LZ1  DLW21HN900HQ2L_4P  [MURAT_DLW21HN900HQ2L_4P]  110.09 113.27 180 bottom
NOREF  -  []  -49.72 47.49 0 top
NOREF#2  -  []  45.5 34.05 0 top
NOREF#3  -  []  9.7 7.95 0 top
NOREF#4  -  []  231 113.25 270 top
NOREF#5  -  []  50.5 128.65 0 top
NOREF#6  -  []  9.1 46.15 0 top
NOREF#7  -  []  37.53 6.21 0 top
NOREF#8  -  []  103.5 134.45 0 top
NOREF#9  -  []  179.55 114.75 0 top
NOREF#10  -  []  101.35 17.95 0 top
NOREF#11  -  []  66.5 84.45 90 top
NOREF#12  -  []  127.9 138.35 0 top
NOREF#13  -  []  73.72 70.25 0 top
NOREF#14  -  []  87.75 68.79 0 top
NOREF#15  -  []  113.99 -46.26 0 top
NOREF#16  -  []  -51.29 56.16 0 top
NOREF#17  -  []  51.5 133.95 0 top
NOREF#18  -  []  127.9 106.45 0 top
NOREF#19  -  []  57.85 160.65 0 top
NOREF#20  -  []  151.25 89.11 0 top
NOREF#21  -  []  213.45 103.75 0 top
NOREF#22  -  []  193.1 138.35 0 top
NOREF#23  -  []  281.93 130.45 270 top
NOREF#24  -  []  14.2 7.95 0 top
NOREF#25  -  []  80 121.25 0 top
NOREF#26  -  []  217.5 133.45 0 top
NOREF#27  -  []  226.12 52.93 0 top
NOREF#28  -  []  151.25 68.79 0 top
NOREF#29  -  []  -13.33 69.05 0 top
NOREF#30  -  []  -18.79 66.2 0 top
NOREF#31  -  []  262.5 138.52 0 top
NOREF#32  -  []  227.5 17.45 270 top
NOREF#33  -  []  87.75 89.11 0 top
NOREF#34  -  []  82.06 106.52 180 bottom
NOREF#35  -  []  91.43 53.74 180 bottom
NOREF#36  -  []  -7.94 -4.05 180 bottom
NOREF#37  -  []  121.35 54.66 180 bottom
PBATT1  LLTOP_ALLTOP C144LS-109A9-L 9P BATT P2  [ALLTO_C144LS-109A9-L_9P-T]  168.5 2.3 180 bottom
PC1  1U_0603_10V4Z  [C_0603]  215.29 52.12 0 bottom
PC3  2200P_0402_50V7K~D  [C_0402]  155.32 16.18 180 bottom
PC4  1500P_0402_50V7K  [C_0402]  148.21 18.05 0 bottom
PC5  0.022U_0805_50V7K  [C_0805]  72.81 99.41 180 bottom
PC9  1000P_0603_50V7K  [C_0603]  80.08 113.91 0 top
PC10  10U_0805_25V6K  [C_0805]  45.53 39.4 0 top
PC11  0.1U_0603_25V7K  [C_0603]  69.92 101.08 90 top
PC100  4.7U_0603_10V6K  [C_0603]  46.48 29.57 270 top
PC101  10U_0805_25V6K  [C_0805]  40.57 18.15 0 top
PC102  10U_0805_25V6K  [C_0805]  49.61 16.42 180 top
PC105  2200P_0402_50V7K  [C_0402]  40.39 16.87 0 top
PC106  0.1U_0402_25V6  [C_0402]  42.18 15.97 90 top
PC109  0.1U_0603_25V7K  [C_0603]  42.43 26.2 180 top
PC110  0.1U_0603_25V7K  [C_0603]  52.39 26.03 180 top
